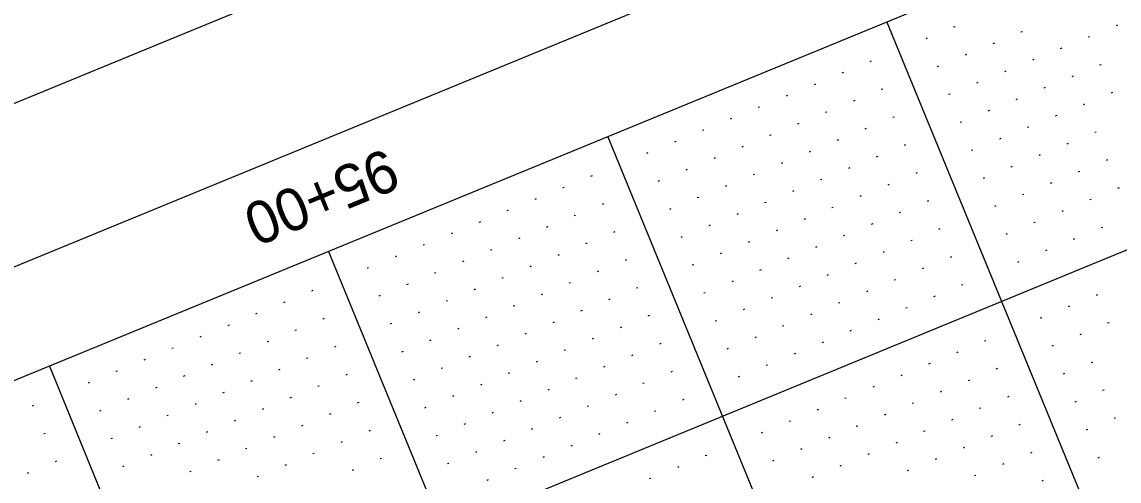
# Model space of a CAD drawing. Extents: x 2148770 to 2150891, y 142633 to 144465.
# Drawn here: x 2149944.3 to 2150126, y 144099.1 to 144175 of the extents above; entities that cross this region are included whole.
import ezdxf

# ---------------------------------------------------------------- set-up
doc = ezdxf.new("R2010")
doc.units = 0
for name, color, linetype in [('SHT_Plan_Profile_Sheet_Sta_Txt', 7, 'Continuous'), ('SHT_Plot_Shape_Half', 7, 'Continuous'), ('SHT_Profile_Grid_Major', 7, 'Continuous'), ('SHT_Profile_Grid_Minor', 7, 'Continuous'), ('SHT_Sheet_Border', 7, 'Continuous')]:
    doc.layers.add(name, color=color, linetype=linetype)

msp = doc.modelspace()

# ---------------------------------------------------------------- linework, layer by layer
at = {"layer": 'SHT_Plot_Shape_Half'}
msp.add_lwpolyline([(2150799.14, 143324.02), (2149226.52, 142678.36), (2148808.74, 143695.93), (2150381.36, 144341.59)], close=True, dxfattribs=at)
at = {"layer": 'SHT_Profile_Grid_Major'}
for p, q in [((2150326.3, 144218.99), (2148869.31, 143620.81)), ((2150087.6, 144175.04), (2150277.5, 143712.51)), ((2150041.35, 144156.05), (2150231.25, 143693.52)), ((2149995.09, 144137.06), (2150184.9, 143674.75)), ((2149948.84, 144118.07), (2150138.65, 143655.76))]:
    msp.add_line(p, q, dxfattribs=at)
at = {"layer": 'SHT_Profile_Grid_Minor'}
for p, q in [((2150098.87, 144174.26), (2150098.64, 144174.17)), ((2150110.02, 144173.44), (2150109.79, 144173.34)), ((2150125.79, 144174.51), (2150125.56, 144174.41)), ((2150094.24, 144172.36), (2150094.01, 144172.27)), ((2150105.39, 144171.54), (2150105.16, 144171.44)), ((2150121.17, 144172.61), (2150120.93, 144172.51)), ((2150100.77, 144169.64), (2150100.53, 144169.54)), ((2150116.54, 144170.71), (2150116.31, 144170.61)), ((2150084.99, 144168.57), (2150084.76, 144168.47)), ((2150096.14, 144167.74), (2150095.91, 144167.64)), ((2150111.92, 144168.81), (2150111.68, 144168.72)), ((2150123.07, 144167.98), (2150122.83, 144167.89)), ((2150080.37, 144166.67), (2150080.13, 144166.57)), ((2150107.29, 144166.91), (2150107.06, 144166.82)), ((2150118.44, 144166.08), (2150118.21, 144165.99)), ((2150075.74, 144164.77), (2150075.51, 144164.67)), ((2150102.66, 144165.01), (2150102.43, 144164.92)), ((2150113.81, 144164.18), (2150113.58, 144164.09)), ((2150071.11, 144162.87), (2150070.88, 144162.77)), ((2150086.89, 144163.94), (2150086.66, 144163.85)), ((2150098.04, 144163.11), (2150097.81, 144163.02)), ((2150109.19, 144162.29), (2150108.96, 144162.19)), ((2150124.96, 144163.36), (2150124.73, 144163.26)), ((2150066.49, 144160.97), (2150066.26, 144160.87)), ((2150082.26, 144162.04), (2150082.03, 144161.95)), ((2150120.34, 144161.46), (2150120.11, 144161.36)), ((2150061.86, 144159.07), (2150061.63, 144158.98)), ((2150077.64, 144160.14), (2150077.41, 144160.05)), ((2150088.79, 144159.32), (2150088.56, 144159.22)), ((2150104.56, 144160.39), (2150104.33, 144160.29)), ((2150115.71, 144159.56), (2150115.48, 144159.46)), ((2150057.24, 144157.17), (2150057.01, 144157.08)), ((2150073.01, 144158.24), (2150072.78, 144158.15)), ((2150084.16, 144157.42), (2150083.93, 144157.32)), ((2150099.94, 144158.49), (2150099.71, 144158.39)), ((2150111.09, 144157.66), (2150110.86, 144157.57)), ((2150122.24, 144156.83), (2150122.01, 144156.74)), ((2150052.61, 144155.27), (2150052.38, 144155.18)), ((2150068.39, 144156.34), (2150068.16, 144156.25)), ((2150079.54, 144155.52), (2150079.31, 144155.42)), ((2150106.46, 144155.76), (2150106.23, 144155.67)), ((2150047.99, 144153.37), (2150047.76, 144153.28)), ((2150063.76, 144154.45), (2150063.53, 144154.35)), ((2150074.91, 144153.62), (2150074.68, 144153.52)), ((2150090.69, 144154.69), (2150090.46, 144154.59)), ((2150101.84, 144153.86), (2150101.61, 144153.77)), ((2150117.61, 144154.93), (2150117.38, 144154.84)), ((2150059.14, 144152.55), (2150058.91, 144152.45)), ((2150070.29, 144151.72), (2150070.06, 144151.62)), ((2150086.06, 144152.79), (2150085.83, 144152.7)), ((2150112.99, 144153.04), (2150112.76, 144152.94)), ((2150124.14, 144152.21), (2150123.91, 144152.11)), ((2150038.74, 144149.58), (2150038.51, 144149.48)), ((2150054.51, 144150.65), (2150054.28, 144150.55)), ((2150065.66, 144149.82), (2150065.43, 144149.73)), ((2150081.44, 144150.89), (2150081.21, 144150.8)), ((2150092.59, 144150.06), (2150092.36, 144149.97)), ((2150108.36, 144151.14), (2150108.13, 144151.04)), ((2150119.51, 144150.31), (2150119.28, 144150.21)), ((2150049.89, 144148.75), (2150049.66, 144148.65)), ((2150061.04, 144147.92), (2150060.81, 144147.83)), ((2150076.81, 144148.99), (2150076.58, 144148.9)), ((2150087.96, 144148.17), (2150087.73, 144148.07)), ((2150103.74, 144149.24), (2150103.51, 144149.14)), ((2150114.89, 144148.41), (2150114.65, 144148.31)), ((2150034.11, 144147.68), (2150033.88, 144147.58)), ((2150056.41, 144146.02), (2150056.18, 144145.93)), ((2150072.19, 144147.09), (2150071.96, 144147)), ((2150083.34, 144146.27), (2150083.1, 144146.17)), ((2150110.26, 144146.51), (2150110.03, 144146.42)), ((2150126.04, 144147.58), (2150125.8, 144147.49)), ((2150029.49, 144145.78), (2150029.26, 144145.68)), ((2150040.64, 144144.95), (2150040.41, 144144.86)), ((2150051.79, 144144.12), (2150051.55, 144144.03)), ((2150067.56, 144145.19), (2150067.33, 144145.1)), ((2150078.71, 144144.37), (2150078.48, 144144.27)), ((2150094.49, 144145.44), (2150094.25, 144145.34)), ((2150105.64, 144144.61), (2150105.4, 144144.52)), ((2150121.41, 144145.68), (2150121.18, 144145.59)), ((2150024.86, 144143.88), (2150024.63, 144143.78)), ((2150036.01, 144143.05), (2150035.78, 144142.96)), ((2150062.94, 144143.3), (2150062.7, 144143.2)), ((2150074.09, 144142.47), (2150073.85, 144142.37)), ((2150089.86, 144143.54), (2150089.63, 144143.45)), ((2150116.79, 144143.78), (2150116.55, 144143.69)), ((2150020.24, 144141.98), (2150020, 144141.88)), ((2150031.39, 144141.15), (2150031.15, 144141.06)), ((2150058.31, 144141.4), (2150058.08, 144141.3)), ((2150069.46, 144140.57), (2150069.23, 144140.47)), ((2150085.24, 144141.64), (2150085, 144141.55)), ((2150096.38, 144140.81), (2150096.15, 144140.72)), ((2150112.16, 144141.89), (2150111.93, 144141.79)), ((2150123.31, 144141.06), (2150123.08, 144140.96)), ((2150015.61, 144140.08), (2150015.38, 144139.99)), ((2150026.76, 144139.25), (2150026.53, 144139.16)), ((2150042.54, 144140.33), (2150042.3, 144140.23)), ((2150053.69, 144139.5), (2150053.45, 144139.4)), ((2150064.83, 144138.67), (2150064.6, 144138.58)), ((2150080.61, 144139.74), (2150080.38, 144139.65)), ((2150091.76, 144138.91), (2150091.53, 144138.82)), ((2150107.53, 144139.99), (2150107.3, 144139.89)), ((2150118.68, 144139.16), (2150118.45, 144139.06)), ((2150010.99, 144138.18), (2150010.75, 144138.09)), ((2150022.13, 144137.35), (2150021.9, 144137.26)), ((2150037.91, 144138.43), (2150037.68, 144138.33)), ((2150075.98, 144137.84), (2150075.75, 144137.75)), ((2150087.13, 144137.02), (2150086.9, 144136.92)), ((2150114.06, 144137.26), (2150113.83, 144137.17)), ((2150006.36, 144136.28), (2150006.13, 144136.19)), ((2150017.51, 144135.46), (2150017.28, 144135.36)), ((2150033.28, 144136.53), (2150033.05, 144136.43)), ((2150044.43, 144135.7), (2150044.2, 144135.6)), ((2150060.21, 144136.77), (2150059.98, 144136.68)), ((2150071.36, 144135.94), (2150071.13, 144135.85)), ((2150082.51, 144135.12), (2150082.28, 144135.02)), ((2150098.28, 144136.19), (2150098.05, 144136.09)), ((2150109.43, 144135.36), (2150109.2, 144135.27)), ((2150001.73, 144134.38), (2150001.5, 144134.29)), ((2150012.88, 144133.56), (2150012.65, 144133.46)), ((2150028.66, 144134.63), (2150028.43, 144134.53)), ((2150039.81, 144133.8), (2150039.58, 144133.71)), ((2150055.58, 144134.87), (2150055.35, 144134.78)), ((2150066.73, 144134.05), (2150066.5, 144133.95)), ((2150077.88, 144133.22), (2150077.65, 144133.12)), ((2150093.66, 144134.29), (2150093.43, 144134.19)), ((2150008.26, 144131.66), (2150008.03, 144131.56)), ((2150024.03, 144132.73), (2150023.8, 144132.63)), ((2150035.18, 144131.9), (2150034.95, 144131.81)), ((2150062.11, 144132.15), (2150061.88, 144132.05)), ((2150089.03, 144132.39), (2150088.8, 144132.3)), ((2150100.18, 144131.56), (2150099.95, 144131.47)), ((2149992.48, 144130.59), (2149992.25, 144130.49)), ((2150003.63, 144129.76), (2150003.4, 144129.66)), ((2150019.41, 144130.83), (2150019.18, 144130.74)), ((2150030.56, 144130), (2150030.33, 144129.91)), ((2150046.33, 144131.07), (2150046.1, 144130.98)), ((2150057.48, 144130.25), (2150057.25, 144130.15)), ((2150073.26, 144131.32), (2150073.03, 144131.22)), ((2150084.41, 144130.49), (2150084.18, 144130.4)), ((2150095.56, 144129.66), (2150095.33, 144129.57)), ((2150122.48, 144129.91), (2150122.25, 144129.81)), ((2149987.86, 144128.69), (2149987.63, 144128.59)), ((2150014.78, 144128.93), (2150014.55, 144128.84)), ((2150025.93, 144128.1), (2150025.7, 144128.01)), ((2150041.71, 144129.18), (2150041.48, 144129.08)), ((2150068.63, 144129.42), (2150068.4, 144129.32)), ((2150079.78, 144128.59), (2150079.55, 144128.5)), ((2150090.93, 144127.77), (2150090.7, 144127.67)), ((2150117.86, 144128.01), (2150117.63, 144127.91)), ((2149983.23, 144126.79), (2149983, 144126.69)), ((2149994.38, 144125.96), (2149994.15, 144125.87)), ((2150010.16, 144127.03), (2150009.93, 144126.94)), ((2150021.31, 144126.2), (2150021.08, 144126.11)), ((2150037.08, 144127.28), (2150036.85, 144127.18)), ((2150048.23, 144126.45), (2150048, 144126.35)), ((2150064.01, 144127.52), (2150063.78, 144127.43)), ((2150075.16, 144126.69), (2150074.93, 144126.6)), ((2150113.23, 144126.11), (2150113, 144126.02)), ((2149978.61, 144124.89), (2149978.38, 144124.79)), ((2150005.53, 144125.13), (2150005.3, 144125.04)), ((2150016.68, 144124.31), (2150016.45, 144124.21)), ((2150032.46, 144125.38), (2150032.23, 144125.28)), ((2150043.61, 144124.55), (2150043.38, 144124.46)), ((2150059.38, 144125.62), (2150059.15, 144125.53)), ((2150070.53, 144124.79), (2150070.3, 144124.7)), ((2150086.31, 144125.87), (2150086.08, 144125.77)), ((2150124.38, 144125.28), (2150124.15, 144125.19)), ((2149973.98, 144122.99), (2149973.75, 144122.89)), ((2149989.76, 144124.06), (2149989.53, 144123.97)), ((2150012.06, 144122.41), (2150011.83, 144122.31)), ((2150027.83, 144123.48), (2150027.6, 144123.38)), ((2150038.98, 144122.65), (2150038.75, 144122.56)), ((2150065.91, 144122.9), (2150065.68, 144122.8)), ((2150081.68, 144123.97), (2150081.45, 144123.87)), ((2150103.98, 144122.31), (2150103.75, 144122.22)), ((2150119.76, 144123.38), (2150119.52, 144123.29)), ((2149969.36, 144121.09), (2149969.13, 144121)), ((2149985.13, 144122.16), (2149984.9, 144122.07)), ((2149996.28, 144121.34), (2149996.05, 144121.24)), ((2150007.43, 144120.51), (2150007.2, 144120.41)), ((2150023.21, 144121.58), (2150022.98, 144121.48)), ((2150034.36, 144120.75), (2150034.13, 144120.66)), ((2150050.13, 144121.82), (2150049.9, 144121.73)), ((2150061.28, 144121), (2150061.05, 144120.9)), ((2150077.06, 144122.07), (2150076.82, 144121.97)), ((2150115.13, 144121.49), (2150114.9, 144121.39)), ((2149964.73, 144119.19), (2149964.5, 144119.1)), ((2149980.51, 144120.26), (2149980.28, 144120.17)), ((2149991.66, 144119.44), (2149991.43, 144119.34)), ((2150018.58, 144119.68), (2150018.35, 144119.59)), ((2150029.73, 144118.85), (2150029.5, 144118.76)), ((2150045.51, 144119.92), (2150045.27, 144119.83)), ((2150072.43, 144120.17), (2150072.2, 144120.07)), ((2150099.36, 144120.41), (2150099.12, 144120.32)), ((2150121.65, 144118.76), (2150121.42, 144118.66)), ((2149960.11, 144117.29), (2149959.88, 144117.2)), ((2149975.88, 144118.36), (2149975.65, 144118.27)), ((2149987.03, 144117.54), (2149986.8, 144117.44)), ((2150013.96, 144117.78), (2150013.72, 144117.69)), ((2150025.11, 144116.95), (2150024.87, 144116.86)), ((2150040.88, 144118.03), (2150040.65, 144117.93)), ((2150052.03, 144117.2), (2150051.8, 144117.1)), ((2150067.81, 144118.27), (2150067.57, 144118.18)), ((2150094.73, 144118.51), (2150094.5, 144118.42)), ((2150105.88, 144117.69), (2150105.65, 144117.59)), ((2150117.03, 144116.86), (2150116.8, 144116.76)), ((2149955.48, 144115.39), (2149955.25, 144115.3)), ((2149971.26, 144116.47), (2149971.02, 144116.37)), ((2149982.41, 144115.64), (2149982.17, 144115.54)), ((2149998.18, 144116.71), (2149997.95, 144116.61)), ((2150009.33, 144115.88), (2150009.1, 144115.79)), ((2150020.48, 144115.06), (2150020.25, 144114.96)), ((2150036.26, 144116.13), (2150036.02, 144116.03)), ((2150047.4, 144115.3), (2150047.17, 144115.2)), ((2150063.18, 144116.37), (2150062.95, 144116.28)), ((2150090.1, 144116.62), (2150089.87, 144116.52)), ((2150101.25, 144115.79), (2150101.02, 144115.69)), ((2149966.63, 144114.57), (2149966.4, 144114.47)), ((2149977.78, 144113.74), (2149977.55, 144113.64)), ((2149993.56, 144114.81), (2149993.32, 144114.72)), ((2150031.63, 144114.23), (2150031.4, 144114.13)), ((2150042.78, 144113.4), (2150042.55, 144113.31)), ((2150085.48, 144114.72), (2150085.25, 144114.62)), ((2150096.63, 144113.89), (2150096.4, 144113.79)), ((2150123.55, 144114.13), (2150123.32, 144114.04)), ((2149946.23, 144111.6), (2149946, 144111.5)), ((2149962.01, 144112.67), (2149961.77, 144112.57)), ((2149973.16, 144111.84), (2149972.92, 144111.75)), ((2149988.93, 144112.91), (2149988.7, 144112.82)), ((2150000.08, 144112.08), (2149999.85, 144111.99)), ((2150015.85, 144113.16), (2150015.62, 144113.06)), ((2150027, 144112.33), (2150026.77, 144112.23)), ((2150038.15, 144111.5), (2150037.92, 144111.41)), ((2150053.93, 144112.57), (2150053.7, 144112.48)), ((2150080.85, 144112.82), (2150080.62, 144112.72)), ((2150092, 144111.99), (2150091.77, 144111.9)), ((2150107.78, 144113.06), (2150107.55, 144112.97)), ((2150118.93, 144112.23), (2150118.7, 144112.14)), ((2149957.38, 144110.77), (2149957.15, 144110.67)), ((2149968.53, 144109.94), (2149968.3, 144109.85)), ((2149984.3, 144111.01), (2149984.07, 144110.92)), ((2149995.45, 144110.19), (2149995.22, 144110.09)), ((2150011.23, 144111.26), (2150011, 144111.16)), ((2150022.38, 144110.43), (2150022.15, 144110.33)), ((2150033.53, 144109.6), (2150033.3, 144109.51)), ((2150049.3, 144110.67), (2150049.07, 144110.58)), ((2150076.23, 144110.92), (2150076, 144110.82)), ((2150087.38, 144110.09), (2150087.15, 144110)), ((2150103.15, 144111.16), (2150102.92, 144111.07)), ((2149963.9, 144108.04), (2149963.67, 144107.95)), ((2149979.68, 144109.11), (2149979.45, 144109.02)), ((2149990.83, 144108.29), (2149990.6, 144108.19)), ((2150017.75, 144108.53), (2150017.52, 144108.44)), ((2150044.68, 144108.78), (2150044.45, 144108.68)), ((2150071.6, 144109.02), (2150071.37, 144108.92)), ((2150082.75, 144108.19), (2150082.52, 144108.1)), ((2150098.53, 144109.26), (2150098.3, 144109.17)), ((2150109.68, 144108.44), (2150109.45, 144108.34)), ((2150125.45, 144109.51), (2150125.22, 144109.41)), ((2149948.13, 144106.97), (2149947.9, 144106.88)), ((2149959.28, 144106.14), (2149959.05, 144106.05)), ((2149975.05, 144107.21), (2149974.82, 144107.12)), ((2149986.2, 144106.39), (2149985.97, 144106.29)), ((2150001.98, 144107.46), (2150001.75, 144107.36)), ((2150013.13, 144106.63), (2150012.9, 144106.54)), ((2150028.9, 144107.7), (2150028.67, 144107.61)), ((2150040.05, 144106.88), (2150039.82, 144106.78)), ((2150066.98, 144107.12), (2150066.75, 144107.03)), ((2150078.13, 144106.29), (2150077.9, 144106.2)), ((2150093.9, 144107.36), (2150093.67, 144107.27)), ((2150105.05, 144106.54), (2150104.82, 144106.44)), ((2150120.83, 144107.61), (2150120.6, 144107.51)), ((2149970.43, 144105.32), (2149970.2, 144105.22)), ((2149981.58, 144104.49), (2149981.35, 144104.39)), ((2149997.35, 144105.56), (2149997.12, 144105.47)), ((2150024.28, 144105.8), (2150024.05, 144105.71)), ((2150035.43, 144104.98), (2150035.2, 144104.88)), ((2150073.5, 144104.39), (2150073.27, 144104.3)), ((2150089.28, 144105.47), (2150089.05, 144105.37)), ((2150100.43, 144104.64), (2150100.2, 144104.54)), ((2149950.03, 144102.35), (2149949.8, 144102.25)), ((2149965.8, 144103.42), (2149965.57, 144103.32)), ((2149976.95, 144102.59), (2149976.72, 144102.49)), ((2149992.73, 144103.66), (2149992.5, 144103.57)), ((2150003.88, 144102.83), (2150003.65, 144102.74)), ((2150019.65, 144103.91), (2150019.42, 144103.81)), ((2150030.8, 144103.08), (2150030.57, 144102.98)), ((2150057.73, 144103.32), (2150057.5, 144103.23)), ((2150068.88, 144102.5), (2150068.65, 144102.4)), ((2150084.65, 144103.57), (2150084.42, 144103.47)), ((2150095.8, 144102.74), (2150095.57, 144102.64)), ((2150111.58, 144103.81), (2150111.35, 144103.72)), ((2150122.73, 144102.98), (2150122.5, 144102.89)), ((2149961.18, 144101.52), (2149960.95, 144101.42)), ((2149972.33, 144100.69), (2149972.1, 144100.6)), ((2149988.1, 144101.76), (2149987.87, 144101.67)), ((2149999.25, 144100.93), (2149999.02, 144100.84)), ((2150015.03, 144102.01), (2150014.8, 144101.91)), ((2150026.18, 144101.18), (2150025.95, 144101.08)), ((2150053.1, 144101.42), (2150052.87, 144101.33)), ((2150080.03, 144101.67), (2150079.8, 144101.57)), ((2150091.18, 144100.84), (2150090.95, 144100.75)), ((2150106.95, 144101.91), (2150106.72, 144101.82)), ((2149945.4, 144100.45), (2149945.17, 144100.35)), ((2149983.48, 144099.86), (2149983.25, 144099.77)), ((2150021.55, 144099.28), (2150021.32, 144099.19)), ((2150048.48, 144099.52), (2150048.25, 144099.43)), ((2150075.4, 144099.77), (2150075.17, 144099.67)), ((2150102.33, 144100.01), (2150102.09, 144099.92)), ((2150113.48, 144099.19), (2150113.24, 144099.09))]:
    msp.add_line(p, q, dxfattribs=at)
at = {"layer": 'SHT_Sheet_Border'}
msp.add_line((2150307.31, 144265.25), (2149093.15, 143766.76), dxfattribs=at)
msp.add_lwpolyline([(2150699.45, 143310.11), (2149242.47, 142711.93), (2148843.68, 143683.25), (2150300.66, 144281.43)], close=True, dxfattribs=at)

# ---------------------------------------------------------------- texts
at = {"layer": 'SHT_Plan_Profile_Sheet_Sta_Txt'}
msp.add_text('95+00', height=7, rotation=202.3213, dxfattribs=at).set_placement((2150004.78, 144154.28))

doc.saveas('drawing.dxf')
